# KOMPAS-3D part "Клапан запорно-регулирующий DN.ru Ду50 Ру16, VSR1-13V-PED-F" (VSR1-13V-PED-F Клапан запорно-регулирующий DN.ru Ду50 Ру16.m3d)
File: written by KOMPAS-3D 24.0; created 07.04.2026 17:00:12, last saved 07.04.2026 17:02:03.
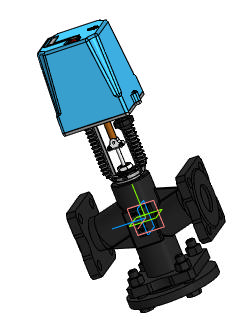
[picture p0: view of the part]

Document properties: Автор: R2D2; Полное имя файла: E:\Работа\Зайцев\Солянка\VSR1-13V-PED-F Клапан запорно-регулирующий DN.ru\DN50\VSR1-13V-PED-F Клапан запорно-регулирующий DN.ru Ду50 Ру16.m3d

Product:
- Part/product: Клапан запорно-регулирующий DN.ru Ду50 Ру16  | designation VSR1-13V-PED-F
    Масса: 13.7
    Раздел спецификации: Прочие изделия
    Примечание: D090-02891

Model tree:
1. Операция без истории:1  (labels: SHAPEOBJECT3D_ATTR_BUTT)

Expressions: VSR1-13V-PED-F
